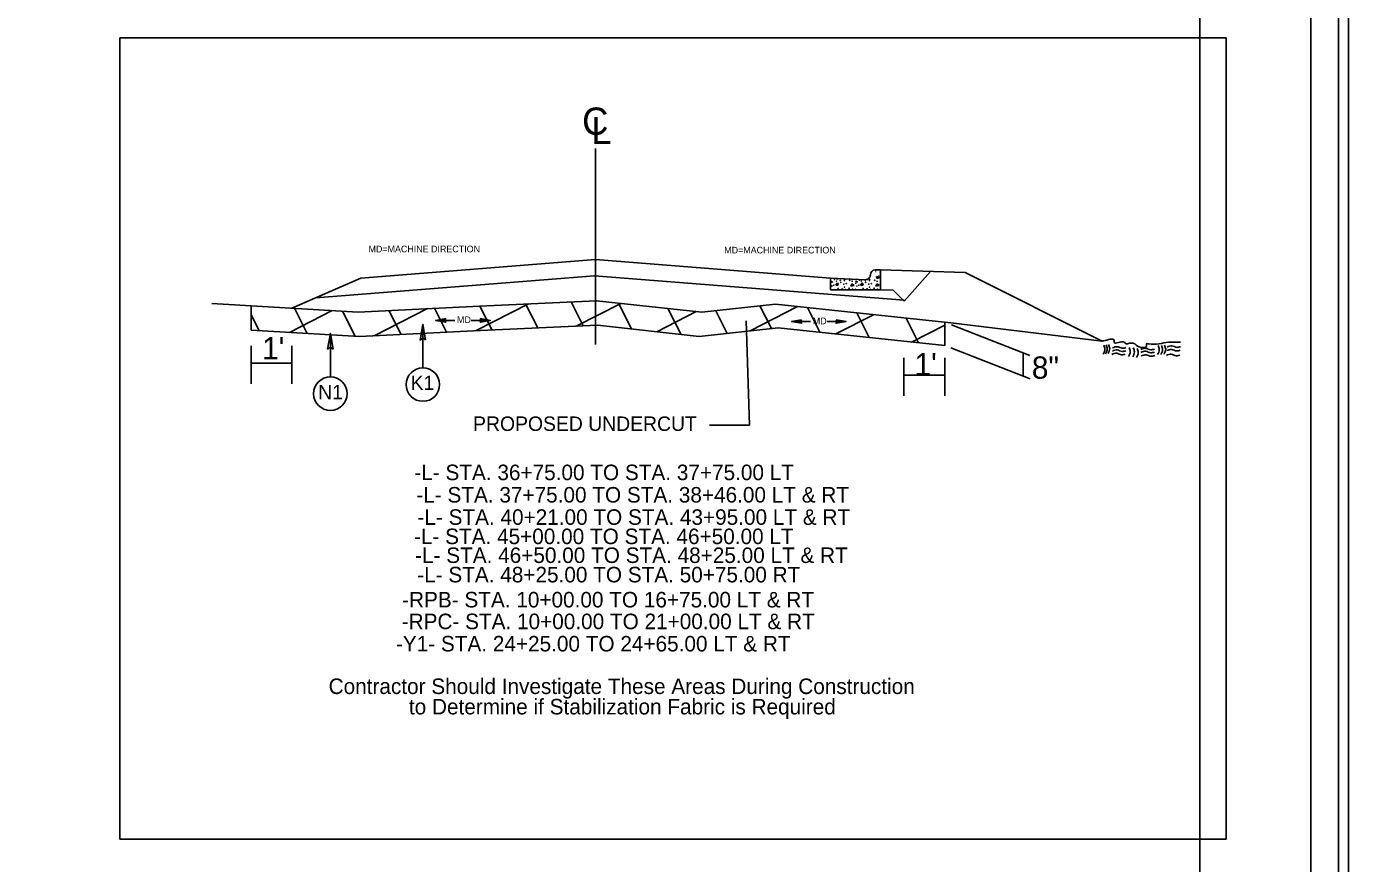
# Model space of a CAD drawing. Extents: x 1640342 to 1730599, y 538663 to 843747.
# Drawn here: x 1730058.2 to 1730177.4, y 539955 to 540030.6 of the extents above; entities that cross this region are included whole.
import ezdxf

# ---------------------------------------------------------------- set-up
doc = ezdxf.new("R2010")
doc.units = 0
for name, color, linetype in [('Old_Level_11', 7, 'Continuous'), ('Old_Level_3', 7, 'Continuous'), ('Prop Dimension', 7, 'Continuous'), ('Prop Terminator CELL', 7, 'Continuous'), ('Prop XS Undercut Exc', 7, 'Continuous'), ('Sheet Clip Boundary CELL', 7, 'Continuous'), ('Sheet Layout Plan Border', 7, 'Continuous'), ('Sheet Plan CELL', 7, 'Continuous'), ('Sheet Plan Layout CELL', 7, 'Continuous'), ('Sheet Plot Border Inside CELL', 7, 'Continuous'), ('Sheet Plot Border Outside CELL', 7, 'Continuous'), ('Typical Detail Wedge2 CELL', 7, 'Continuous'), ('Typical Hinge Slope Interstate CELL', 7, 'Continuous'), ('Typical ID Circle CELL', 7, 'Continuous'), ('Typical Pavement Slope CELL', 7, 'Continuous'), ('Typical Terminator CELL', 7, 'Continuous'), ('Typical Text Centerline CELL', 7, 'Continuous'), ('Typical Text General CELL', 7, 'Continuous'), ('Typical Text Label CELL', 7, 'Continuous')]:
    doc.layers.add(name, color=color, linetype=linetype)

msp = doc.modelspace()

# ---------------------------------------------------------------- linework, layer by layer
at = {"layer": 'Old_Level_11'}
for p, q in [((1730109.49, 540019.53), (1730109.49, 540001.86)), ((1730123.37, 539994.6), (1730123.07, 540004)), ((1730141.57, 540003.64), (1730148.66, 540000.86)), ((1730078.42, 540001.74), (1730078.42, 539998.32)), ((1730082.09, 540001.74), (1730082.09, 539998.32)), ((1730141.52, 540001.56), (1730148.67, 539998.77)), ((1730148.05, 540001.1), (1730148.05, 539999.01)), ((1730078.46, 540000.18), (1730082.09, 540000.18)), ((1730137.3, 540000.67), (1730137.3, 539997.25)), ((1730140.97, 540000.67), (1730140.97, 539997.25)), ((1730137.34, 539999.11), (1730140.97, 539999.11)), ((1730119.75, 539994.6), (1730123.37, 539994.6))]:
    msp.add_line(p, q, dxfattribs=at)
at = {"layer": 'Prop Dimension'}
for p, q in [((1730096.78, 540004.04), (1730095.07, 540004.04)), ((1730098.28, 540004.04), (1730099.99, 540004.04)), ((1730128.87, 540003.94), (1730127.16, 540003.94)), ((1730130.36, 540003.94), (1730132.07, 540003.94))]:
    msp.add_line(p, q, dxfattribs=at)
at = {"layer": 'Prop Terminator CELL'}
for points in [[(1730095.97, 540004.2), (1730095.07, 540004.04), (1730095.98, 540003.88), (1730095.86, 540004.04)], [(1730099.09, 540004.2), (1730099.99, 540004.04), (1730099.08, 540003.88), (1730099.2, 540004.04)], [(1730128.06, 540004.09), (1730127.16, 540003.94), (1730128.06, 540003.78), (1730127.95, 540003.94)], [(1730131.17, 540004.09), (1730132.07, 540003.94), (1730131.17, 540003.78), (1730131.28, 540003.94)]]:
    msp.add_lwpolyline(points, close=True, dxfattribs=at)
at = {"layer": 'Prop XS Undercut Exc'}
for p, q in [((1730108.38, 540003.54), (1730107.28, 540005.71)), ((1730078.42, 540005.37), (1730078.42, 540003.16)), ((1730079.14, 540003.12), (1730078.42, 540004.53)), ((1730081.87, 540002.96), (1730085.74, 540004.93)), ((1730083.48, 540002.86), (1730082.32, 540005.13)), ((1730087.81, 540002.61), (1730086.66, 540004.88)), ((1730089.52, 540002.65), (1730094.33, 540005.1)), ((1730091.94, 540002.77), (1730090.84, 540004.93)), ((1730096.05, 540002.97), (1730094.95, 540005.13)), ((1730098.67, 540003.1), (1730103.43, 540005.53)), ((1730100.15, 540003.17), (1730099.05, 540005.33)), ((1730104.27, 540003.36), (1730103.17, 540005.52)), ((1730107.73, 540003.52), (1730111.76, 540005.57)), ((1730112.73, 540003.27), (1730111.55, 540005.59)), ((1730115.01, 540003.02), (1730118.56, 540004.83)), ((1730117.19, 540002.78), (1730116, 540005.11)), ((1730121.35, 540002.87), (1730120.32, 540004.91)), ((1730123.43, 540003.1), (1730127.71, 540005.28)), ((1730125.34, 540003.31), (1730124.3, 540005.34)), ((1730129.72, 540002.97), (1730128.59, 540005.19)), ((1730131.14, 540002.82), (1730134.54, 540004.55)), ((1730134.17, 540002.5), (1730133.04, 540004.71)), ((1730099.12, 540003.12), (1730109.66, 540003.6)), ((1730109.66, 540003.6), (1730118.84, 540002.6)), ((1730118.84, 540002.6), (1730125.94, 540003.37)), ((1730125.94, 540003.37), (1730140.97, 540001.78)), ((1730138.62, 540002.02), (1730137.49, 540004.24)), ((1730137.97, 540002.09), (1730140.97, 540003.62)), ((1730140.97, 540001.78), (1730140.97, 540003.87)), ((1730078.42, 540003.16), (1730088.19, 540002.59)), ((1730088.19, 540002.59), (1730099.12, 540003.12))]:
    msp.add_line(p, q, dxfattribs=at)
at = {"layer": 'Sheet Clip Boundary CELL'}
msp.add_lwpolyline([(1729883.99, 539867.86), (1730163.99, 539867.86), (1730163.99, 540035.56), (1730126.14, 540035.56), (1730126.14, 540077.86), (1729883.99, 540077.86)], close=True, dxfattribs=at)
at = {"layer": 'Sheet Layout Plan Border'}
msp.add_lwpolyline([(1729883.99, 539867.86), (1730163.99, 539867.86), (1730163.99, 540035.56), (1730126.14, 540035.56), (1730126.14, 540077.86), (1729883.99, 540077.86)], close=True, dxfattribs=at)
at = {"layer": 'Sheet Plan CELL'}
for points in [[(1730174, 540077.86), (1729873.99, 540077.86), (1729873.99, 539867.86), (1730173.99, 539867.86)], [(1729873.99, 539867.86), (1729873.99, 540077.86), (1730133.98, 540077.86), (1730133.99, 540047.85), (1730173.99, 540047.85), (1730173.99, 539867.86)]]:
    msp.add_lwpolyline(points, close=True, dxfattribs=at)
at = {"layer": 'Sheet Plan Layout CELL'}
msp.add_lwpolyline([(1729873.99, 540077.86), (1729873.99, 539867.86), (1730173.99, 539867.86), (1730173.99, 540035.56), (1730126.14, 540035.56), (1730126.14, 540077.86)], close=True, dxfattribs=at)
at = {"layer": 'Sheet Plot Border Inside CELL'}
msp.add_lwpolyline([(1729843.29, 539867.36), (1730176.49, 539867.36), (1730176.49, 540078.36), (1729843.29, 540078.36)], close=True, dxfattribs=at)
at = {"layer": 'Sheet Plot Border Outside CELL'}
msp.add_lwpolyline([(1729840.69, 539863.36), (1730177.39, 539863.36), (1730177.39, 540082.36), (1729840.69, 540082.36)], close=True, dxfattribs=at)
at = {"layer": 'Typical Detail Wedge2 CELL'}
for p, q in [((1730066.59, 539957.24), (1730066.59, 540029.52)), ((1730166.34, 539957.24), (1730166.34, 540029.52))]:
    msp.add_line(p, q, dxfattribs=at)
at = {"layer": 'Typical ID Circle CELL'}
for p, q in [((1730093.91, 539999.77), (1730093.91, 540003.68)), ((1730085.57, 539998.95), (1730085.57, 540002.86))]:
    msp.add_line(p, q, dxfattribs=at)
for centre in [(1730093.91, 539998.25), (1730085.57, 539997.43)]:
    msp.add_circle(centre, 1.51, dxfattribs=at)
at = {"layer": 'Typical Pavement Slope CELL'}
for p, q in [((1730088.31, 540007.84), (1730109.49, 540009.52)), ((1730130.67, 540007.84), (1730109.49, 540009.52)), ((1730084.25, 540006.08), (1730109.38, 540008.07)), ((1730137.32, 540005.86), (1730109.38, 540008.07)), ((1730134.27, 540008.14), (1730134.27, 540008.16)), ((1730135.17, 540008.59), (1730134.7, 540008.59)), ((1730135.17, 540006.79), (1730135.17, 540008.59)), ((1730142.83, 540008.35), (1730135.17, 540008.59)), ((1730137.31, 540005.78), (1730139.7, 540008.45)), ((1730155.16, 540002.18), (1730142.83, 540008.35)), ((1730088.31, 540007.84), (1730082.09, 540005.15)), ((1730130.67, 540006.79), (1730130.67, 540007.84)), ((1730130.67, 540007.84), (1730133.82, 540007.71)), ((1730131.14, 540007.22), (1730131.3, 540007.44)), ((1730131.36, 540007.23), (1730131.14, 540007.22)), ((1730131.3, 540007.44), (1730131.36, 540007.23)), ((1730132.52, 540007.13), (1730132.63, 540007.33)), ((1730132.82, 540007.2), (1730132.52, 540007.13)), ((1730132.63, 540007.33), (1730132.82, 540007.2)), ((1730133.39, 540007.22), (1730133.54, 540007.44)), ((1730133.61, 540007.23), (1730133.39, 540007.22)), ((1730133.54, 540007.44), (1730133.61, 540007.23)), ((1730134.77, 540007.13), (1730134.88, 540007.33)), ((1730135.06, 540007.2), (1730134.77, 540007.13)), ((1730134.83, 540007.99), (1730134.86, 540007.83)), ((1730135.1, 540007.91), (1730134.83, 540007.99)), ((1730134.86, 540007.83), (1730135.1, 540007.91)), ((1730134.88, 540007.33), (1730135.06, 540007.2)), ((1730099.01, 540005.33), (1730109.56, 540005.81)), ((1730109.56, 540005.81), (1730119.07, 540004.77)), ((1730135.17, 540006.79), (1730130.67, 540006.79)), ((1730136.32, 540006.77), (1730135.17, 540006.79)), ((1730136.32, 540006.77), (1730137.31, 540005.78)), ((1730074.87, 540005.57), (1730088.08, 540004.79)), ((1730088.08, 540004.79), (1730099.01, 540005.33)), ((1730119.07, 540004.77), (1730125.71, 540005.49)), ((1730125.71, 540005.49), (1730141.53, 540003.81)), ((1730141.53, 540003.81), (1730155.16, 540002.18))]:
    msp.add_line(p, q, dxfattribs=at)
for centre in [(1730134.76, 540008.45), (1730135.05, 540008.06), (1730135.15, 540008.39), (1730130.69, 540006.84), (1730130.7, 540007.4), (1730130.73, 540007.57), (1730130.8, 540007.14), (1730130.83, 540007.51), (1730130.98, 540007.22), (1730131.03, 540007.73), (1730131.2, 540007.58), (1730131.28, 540007.76), (1730131.36, 540006.92), (1730131.55, 540007.65), (1730131.6, 540007.47), (1730131.73, 540006.88), (1730131.87, 540007.31), (1730131.92, 540007.62), (1730131.93, 540007.04), (1730131.95, 540007.71), (1730132.03, 540006.83), (1730132.1, 540007.36), (1730132.35, 540006.94), (1730132.41, 540007.66), (1730132.63, 540007.57), (1730132.66, 540006.87), (1730132.94, 540006.84), (1730132.95, 540007.4), (1730132.98, 540007.57), (1730133.05, 540007.14), (1730133.08, 540007.51), (1730133.23, 540007.22), (1730133.28, 540007.68), (1730133.45, 540007.58), (1730133.61, 540006.92), (1730133.8, 540007.65), (1730133.85, 540007.47), (1730133.97, 540006.88), (1730134.12, 540007.31), (1730134.17, 540007.62), (1730134.18, 540007.04), (1730134.2, 540007.71), (1730134.28, 540006.83), (1730134.35, 540007.36), (1730134.6, 540006.94), (1730134.66, 540007.66), (1730134.88, 540007.57), (1730134.91, 540006.87), (1730131.07, 540006.8), (1730133.32, 540006.8)]:
    msp.add_circle(centre, 0.0144, dxfattribs=at)
for centre, start, end in [((1730133.84, 540008.14), 267.6155, 0), ((1730134.7, 540008.16), 90, 180)]:
    msp.add_arc(centre, 0.431, start, end, dxfattribs=at)
for points in [[(1730155.16, 540002.18), (1730155.32, 540002.2), (1730156.25, 540002.2), (1730156.25, 540002.07), (1730157.18, 540002.07), (1730157.32, 540001.94), (1730157.45, 540001.94), (1730158.11, 540001.94), (1730158.25, 540001.8), (1730159.18, 540001.8), (1730159.18, 540001.94), (1730159.31, 540001.94), (1730161.17, 540002.07), (1730162.23, 540002.07)], [(1730155.31, 540001.81), (1730155.42, 540001.45), (1730155.27, 540000.99)], [(1730155.52, 540001.84), (1730155.63, 540001.48), (1730155.48, 540001.02)], [(1730155.74, 540001.86), (1730155.85, 540001.5), (1730155.7, 540001.04)], [(1730156.05, 540000.97), (1730156.48, 540001.07), (1730156.93, 540000.94), (1730157.26, 540001)], [(1730156.09, 540001.27), (1730156.53, 540001.37), (1730156.97, 540001.24), (1730157.3, 540001.3)], [(1730156.11, 540001.56), (1730156.54, 540001.67), (1730156.99, 540001.53), (1730157.32, 540001.59)], [(1730157.61, 540001.6), (1730157.71, 540001.24), (1730157.56, 540000.78)], [(1730157.98, 540001.56), (1730158.08, 540001.2), (1730157.94, 540000.74)], [(1730158.32, 540001.51), (1730158.43, 540001.15), (1730158.28, 540000.69)], [(1730158.67, 540001.42), (1730159.11, 540001.52), (1730159.55, 540001.39), (1730159.88, 540001.45)], [(1730158.67, 540001.15), (1730159.11, 540001.25), (1730159.55, 540001.12), (1730159.88, 540001.18)], [(1730158.7, 540000.83), (1730159.13, 540000.94), (1730159.58, 540000.8), (1730159.91, 540000.86)], [(1730160.22, 540001.77), (1730160.32, 540001.41), (1730160.17, 540000.95)], [(1730160.51, 540001.78), (1730160.62, 540001.42), (1730160.47, 540000.96)], [(1730160.8, 540001.81), (1730160.9, 540001.45), (1730160.75, 540000.99)], [(1730160.97, 540000.88), (1730161.4, 540000.98), (1730161.85, 540000.85), (1730162.18, 540000.91)], [(1730161.01, 540001.31), (1730161.44, 540001.42), (1730161.89, 540001.28), (1730162.22, 540001.34)], [(1730161.03, 540001.64), (1730161.46, 540001.74), (1730161.91, 540001.61), (1730162.23, 540001.67)]]:
    msp.add_spline(points, degree=3, dxfattribs=at)
at = {"layer": 'Typical Terminator CELL'}
for points in [[(1730094.15, 540002.28), (1730093.91, 540003.68), (1730093.66, 540002.27), (1730093.91, 540002.45)], [(1730085.81, 540001.46), (1730085.57, 540002.86), (1730085.32, 540001.45), (1730085.57, 540001.63)]]:
    msp.add_lwpolyline(points, close=True, dxfattribs=at)
at = {"layer": 'Typical Text General CELL'}
for p, q in [((1730066.59, 540029.52), (1730166.34, 540029.52)), ((1730066.59, 539957.24), (1730166.34, 539957.24))]:
    msp.add_line(p, q, dxfattribs=at)

# ---------------------------------------------------------------- texts
at = {"layer": 'Old_Level_3'}
msp.add_text('PROPOSED UNDERCUT', height=1.3056, dxfattribs=at).set_placement((1730098.44, 539994.07))
at = {"layer": 'Typical Hinge Slope Interstate CELL'}
for s, p in [('MD=MACHINE DIRECTION', (1730089.01, 540010.18)), ('MD=MACHINE DIRECTION', (1730121.09, 540010.08)), ('MD', (1730096.99, 540003.8)), ('MD', (1730129.08, 540003.69))]:
    msp.add_text(s, height=0.6, dxfattribs=at).set_placement(p)
at = {"layer": 'Typical Pavement Slope CELL'}
for s, height, p in [("1'", 2.008, (1730079.41, 540000.52)), ("1'", 2.008, (1730138.25, 539999.09)), ('8"', 2.008, (1730148.83, 539998.78)), ('K1', 1.3, (1730092.81, 539997.76)), ('N1', 1.3, (1730084.47, 539996.92)), ('-L- STA. 37+75.00 TO STA. 38+46.00 LT & RT', 1.4, (1730093.32, 539987.61)), ('-L- STA. 40+21.00 TO STA. 43+95.00 LT & RT', 1.4, (1730093.42, 539985.6)), ('-L- STA. 45+00.00 TO STA. 46+50.00 LT ', 1.4, (1730093.11, 539983.86)), ('-L- STA. 46+50.00 TO STA. 48+25.00 LT & RT', 1.4, (1730093.21, 539982.16)), ('-L- STA. 48+25.00 TO STA. 50+75.00 RT', 1.4, (1730093.4, 539980.41)), ('Contractor Should Investigate These Areas During Construction', 1.4, (1730085.41, 539970.34)), ('to Determine if Stabilization Fabric is Required', 1.4, (1730092.65, 539968.5))]:
    msp.add_text(s, height=height, dxfattribs=at).set_placement(p)
at = {"layer": 'Typical Text Centerline CELL'}
for s, rotation, p in [('C', 0.0443, (1730108.27, 540020.78)), ('L', 359.9912, (1730109.09, 540019.94))]:
    msp.add_text(s, height=2.46, rotation=rotation, dxfattribs=at).set_placement(p)
at = {"layer": 'Typical Text Label CELL'}
for s, p in [('-L- STA. 36+75.00 TO STA. 37+75.00 LT', (1730093.14, 539989.63)), ('-RPB- STA. 10+00.00 TO 16+75.00 LT & RT', (1730092.04, 539978.15)), ('-RPC- STA. 10+00.00 TO 21+00.00 LT & RT', (1730092, 539976.19)), ('-Y1- STA. 24+25.00 TO 24+65.00 LT & RT', (1730091.48, 539974.18))]:
    msp.add_text(s, height=1.4, dxfattribs=at).set_placement(p)

doc.saveas('drawing.dxf')
